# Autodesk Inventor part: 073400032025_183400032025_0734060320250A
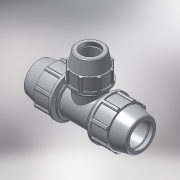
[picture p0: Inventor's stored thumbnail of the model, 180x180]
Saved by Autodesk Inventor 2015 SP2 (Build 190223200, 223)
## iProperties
Created: 2017-02
Part Number: 073400032025_183400032025_0734060320250A
Material: PVC-Piping
Description: PLASSON REDUCING TEE 32-25-32
Document SubType Name: Modeling
Designer: KIM
Mass: 92.6774 g
Surface Area: 199.44 cm^2
Volume: 66.1981 cm^3
Density: 1.4 g/cm^3
Appearance: Smooth - White
Author: Кирилл
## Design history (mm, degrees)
derived "07340.ipt"
feature "Solid1::07340.ipt"
feature "Solid2::07340.ipt"
tag "TaggingFeature1"
body "Solid1"
other parameters: "d2" = 32, "d4" = 7.20833, "d5" = 24.22, "d7" = 64, "d11" = 2.88333, "d13" = 120 deg, "d14" = 48, "d15" = 12 deg, "d16" = 55.68, "d18" = 1.6, "d19" = 35 deg, "d20" = 17.5 deg, "d21" = 59.52, "d23" = 0, "d25" = 360 deg, "d27" = 1.28, "d33" = 0.64, "d42" = 31.14, "d43" = 1.92, "d46" = 0.96, "d67" = 48, "d76" = 25, "d77" = 54, "d78" = 12 deg, "d79" = 83, "d80" = 120 deg, "d81" = 37.5, "d82" = 6.91667, "d87" = 2.76667, "d89" = 20.75, "d90" = 24.9, "d96" = 14.41667, "d98" = 50.22, "d99" = 35 deg, "d100" = 17.5 deg, "d102" = 0, "d103" = 1.08, "d107" = 360 deg, "d109" = 0.75, "d112" = 1.25, "d113" = 3.6, "d114" = 0, "d117" = 173, "d118" = 46.98, "d126" = 28.8, "d127" = 67, "d131" = 3.32, "d132" = 22.5, "d133" = 58, "d135" = 0, "d138" = 3.46, "d143" = 0, "d148" = 40.5, "d168" = 28.8, "d170" = 0, "d171" = 25, "d173" = 0, "d175" = 0, "d176" = 3.6, "d177" = 0, "d_" = 32, "E_" = 64, "A_" = 83, "l_" = 67, "E_1" = 54, "l_1" = 58, "d_1" = 25, "H_" = 173
